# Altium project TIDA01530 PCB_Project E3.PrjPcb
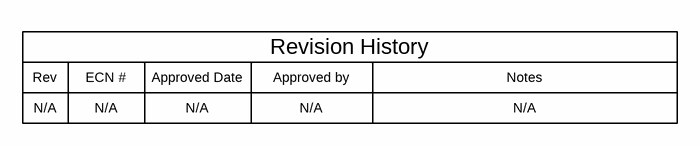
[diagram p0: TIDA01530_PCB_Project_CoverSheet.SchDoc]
CopyrightYear: 2018; PCB_Layout: C.Kinnaird; PCB_Rev: E3; PRJ_Customer: Public Release; PRJ_Engineer: C.Kinnaird; PRJ_Number: TIDA-01530; PRJ_Title: Automotive Windshield Wiper Drive; SCH_Rev: E3; TechSupport: http://www.ti.com/support; TID: 01530
4 sheets, 149 parts. Net scope: global (net labels, ports and power ports of the same name join across sheets).
Board file: TIDA01530E3.PcbDoc
Sheets:
  TIDA01530_PCB_Project_CoverSheet.SchDoc
  TIDA01530 Front Wipers 2x 8702D v2.SchDoc
  TIDA01530 Rear Wipers.SchDoc
  TIDA01530 Switches Connectors.SchDoc

## Sheet TIDA01530_PCB_Project_CoverSheet.SchDoc
size 431 x 279 mm; Date: Not shown in title block; ApprovedBy: Not shown in title block; CheckedBy: Not shown in title block; Author: Not shown in title block; CompanyName: Not shown in title block; Engineer: Not shown in title block; Organization: Not shown in title block; Address1: Not shown in title block; Address2: Not shown in title block; Address3: Not shown in title block; Address4: Not shown in title block; DocumentNumber: 1; Revision: Use project parameter SCH_Rev; SheetNumber: 1; SheetTotal: 4; PageSetup: Record=PageOptions¦CenterHorizontal=True¦CenterVertical=True¦PrintScale=1.00¦XCorrection=1.00¦YCorrection=1.00¦PrintKind=0¦BorderSize=5000000¦LeftOffset=0¦BottomOffset=0¦Orientation=2¦PaperLength=1000¦PaperWidth=1000¦Scale=100¦PaperSource=15¦PrintQuality=600¦MediaType=1¦DitherType=10¦PaperKind=Letter¦PrintScaleMode=1

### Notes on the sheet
- Rev
- N/A
- ECN #
- Approved Date
- Approved by
- Revision History
- Notes

## Sheet TIDA01530 Front Wipers 2x 8702D v2.SchDoc
size 431 x 279 mm; Date: Not shown in title block; ApprovedBy: Not shown in title block; CheckedBy: Not shown in title block; Author: Not shown in title block; CompanyName: Not shown in title block; Engineer: Not shown in title block; Organization: Not shown in title block; Address1: Not shown in title block; Address2: Not shown in title block; Address3: Not shown in title block; Address4: Not shown in title block; DocumentNumber: 1; Revision: Use project parameter SCH_Rev; SheetNumber: 2; SheetTotal: 4; PageSetup: Record=PageOptions¦CenterHorizontal=True¦CenterVertical=True¦PrintScale=1.00¦XCorrection=1.00¦YCorrection=1.00¦PrintKind=0¦BorderSize=5000000¦LeftOffset=0¦BottomOffset=0¦Orientation=2¦PaperLength=1000¦PaperWidth=1000¦Scale=100¦PaperSource=15¦PrintQuality=600¦MediaType=1¦DitherType=10¦PaperKind=Letter¦PrintScaleMode=1
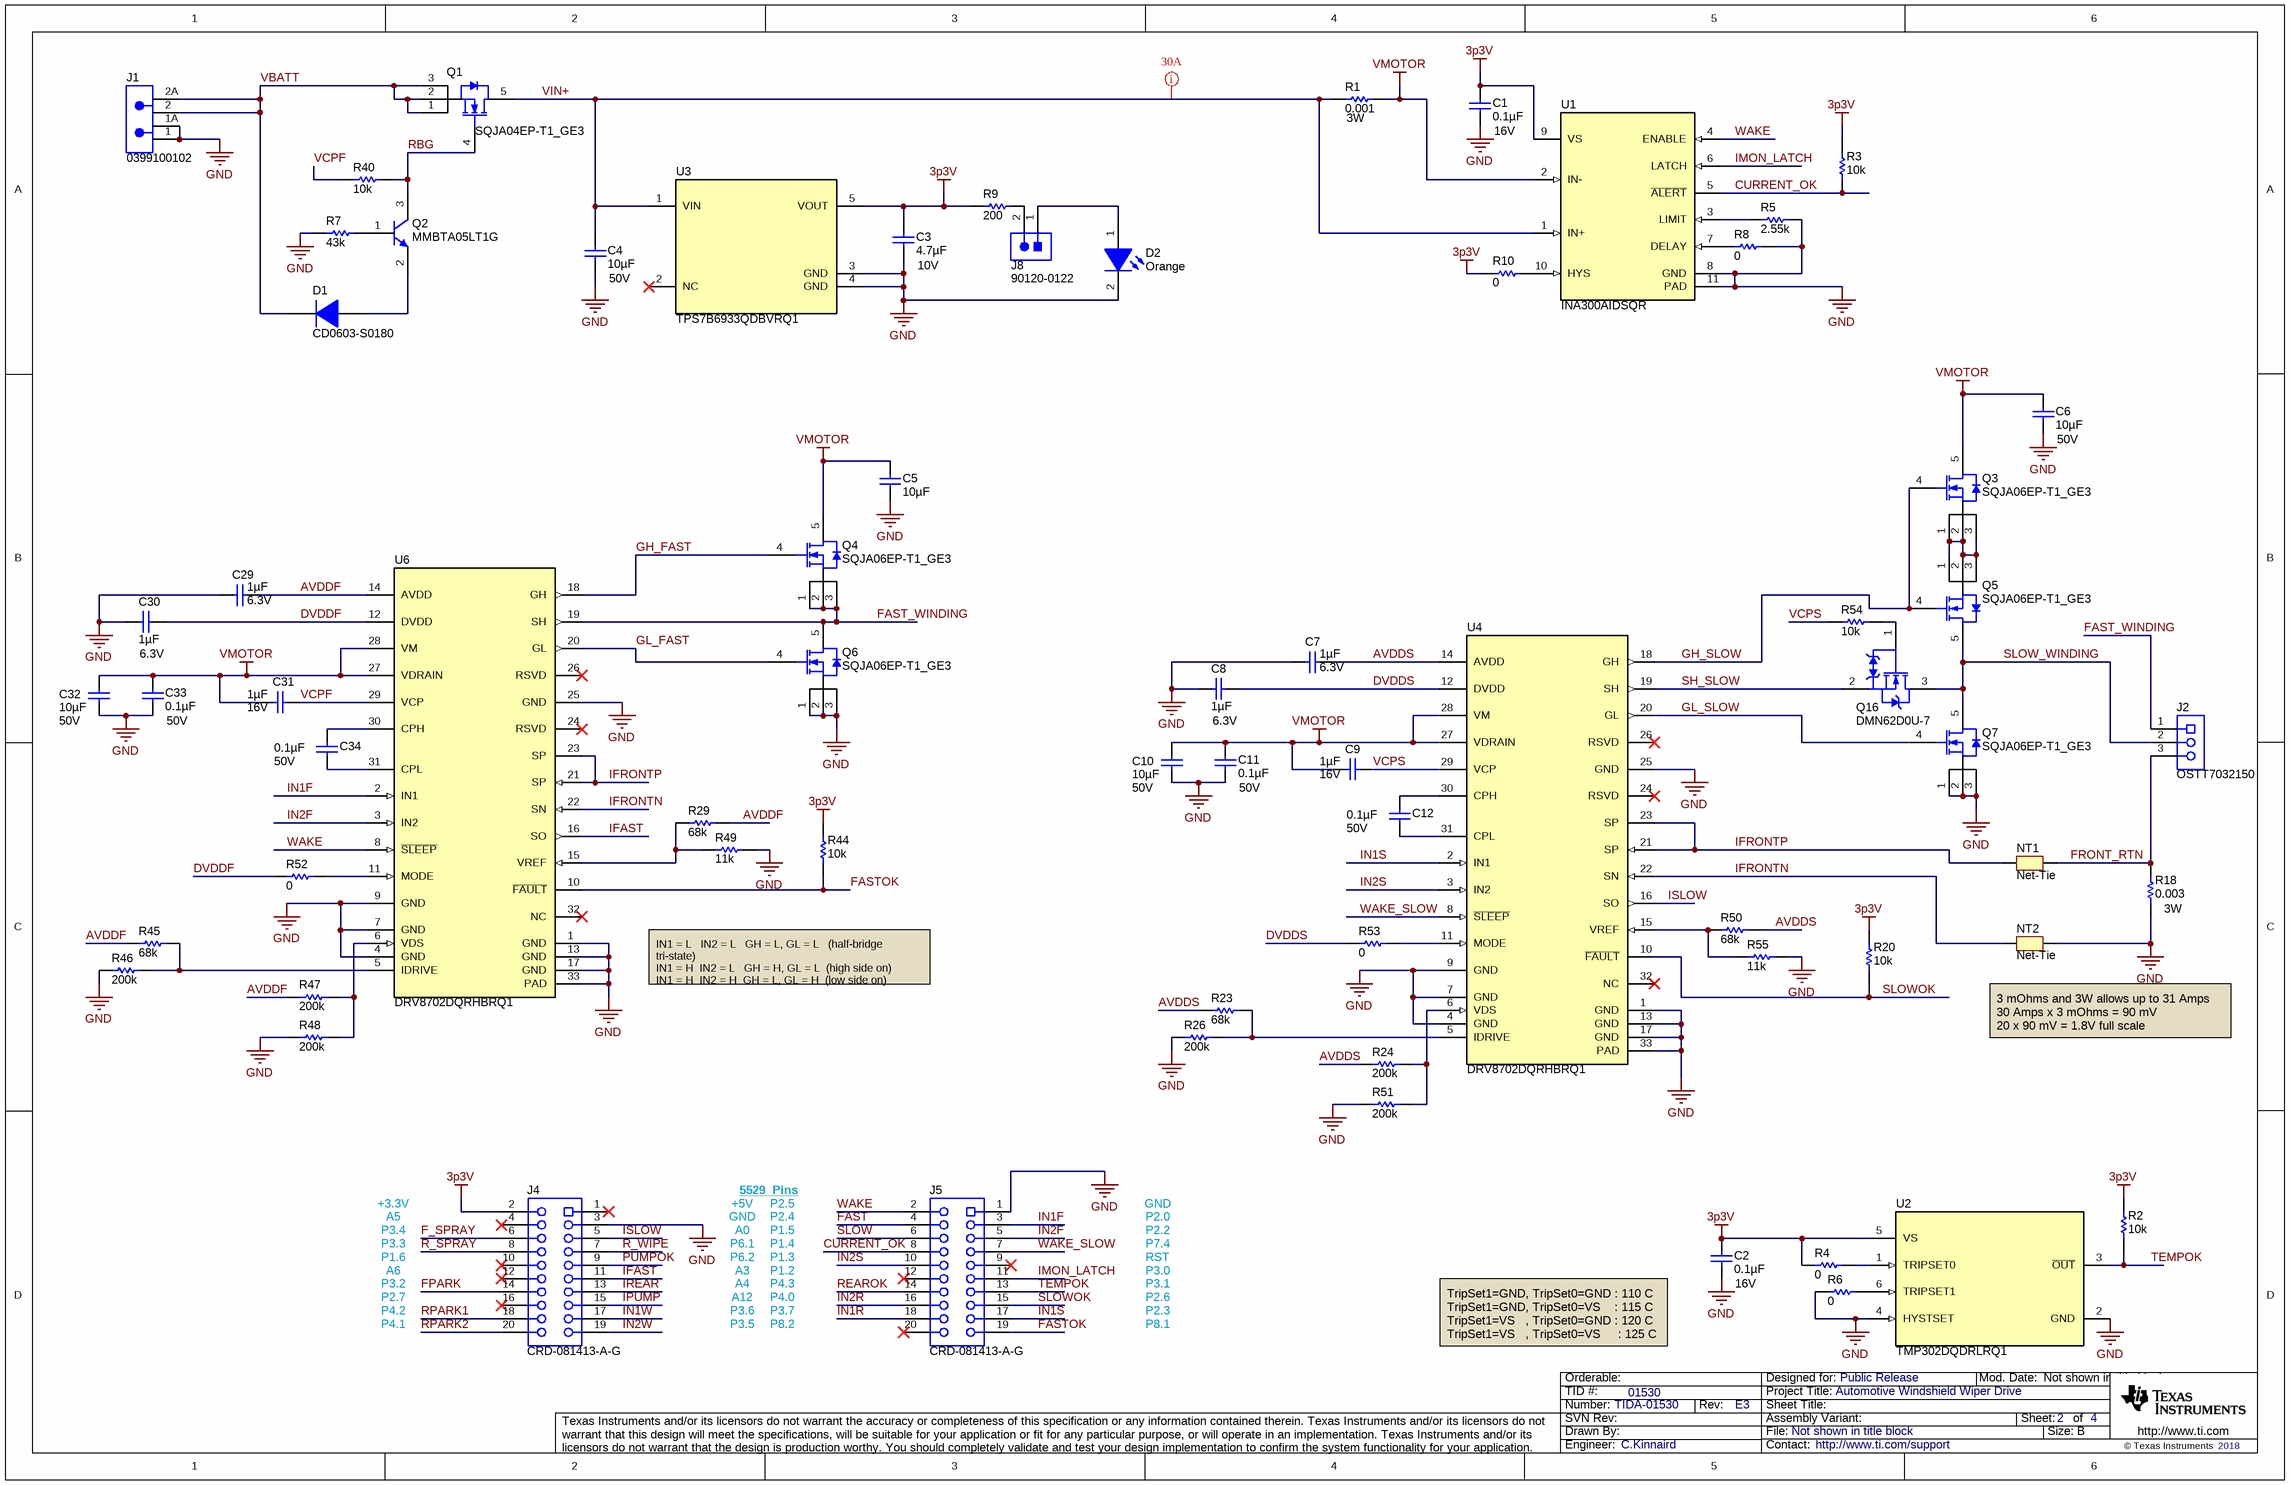
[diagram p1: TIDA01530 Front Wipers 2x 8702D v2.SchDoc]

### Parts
C1  ValueDisplayed: 0.1µF  Value2: 16V  [0402]  (hidden comment: C0402C104K4RACAUTO)
C2  ValueDisplayed: 0.1µF  Value2: 16V  [0402]  (hidden comment: C0402C104K4RACAUTO)
C3  ValueDisplayed: 4.7µF  Value2: 10V  [0805_HV]  (hidden comment: C2012X7R1A475M125AC)
C4  ValueDisplayed: 10µF  Value2: 50V  [1210_280]  (hidden comment: UMK325AB7106KMHT)
C5  ValueDisplayed: 10µF  [1206_180]  (hidden comment: CL31B106KBHNNNE)
C6  ValueDisplayed: 10µF  Value2: 50V  [1206_180]  (hidden comment: CL31B106KBHNNNE)
C7  ValueDisplayed: 1µF  Value2: 6.3V  [0603]  (hidden comment: GRM188R70J105KA01D)
C8  ValueDisplayed: 1µF  Value2: 6.3V  [0603]  (hidden comment: GRM188R70J105KA01D)
C9  ValueDisplayed: 1µF  Value2: 16V  [0603]  (hidden comment: C1608X7R1C105K080AC)
C10  ValueDisplayed: 10µF  Value2: 50V  [1210_280]  (hidden comment: C3225X7S1H106K250AB)
C11  ValueDisplayed: 0.1µF  Value2: 50V  [0603]  (hidden comment: C1608X7R1H104K080AA)
C12  ValueDisplayed: 0.1µF  Value2: 50V  [0603]  (hidden comment: C1608X7R1H104K080AA)
C29  ValueDisplayed: 1µF  Value2: 6.3V  [0603]  (hidden comment: GRM188R70J105KA01D)
C30  ValueDisplayed: 1µF  Value2: 6.3V  [0603]  (hidden comment: GRM188R70J105KA01D)
C31  ValueDisplayed: 1µF  Value2: 16V  [0603]  (hidden comment: C1608X7R1C105K080AC)
C32  ValueDisplayed: 10µF  Value2: 50V  [1210_280]  (hidden comment: C3225X7S1H106K250AB)
C33  ValueDisplayed: 0.1µF  Value2: 50V  [0603]  (hidden comment: C1608X7R1H104K080AA)
C34  ValueDisplayed: 0.1µF  Value2: 50V  [0603]  (hidden comment: C1608X7R1H104K080AA)
D1  CD0603-S0180  [Diode_0603]
D2  value Orange  [LTST-C191_Orange]  (hidden comment: LTST-C191KFKT)
J1  0399100102  [CONN_399100102]
J2  OSTT7032150  [On-Shore_OSTT7032150]
J4  CRD-081413-A-G  [Major_CRD-081413-A-x]
J5  CRD-081413-A-G  [Major_CRD-081413-A-x]
J8  90120-0122  [CONN_90120-0122]
NT1  Net-Tie  [Net-Tie_10mil]  (net tie, no BOM)
NT2  Net-Tie  [Net-Tie_10mil]  (net tie, no BOM)
Q1  SQJA04EP-T1_GE3  [PowerPAK_SO-8L]
Q2  MMBTA05LT1G  [SOT-23]
Q3  SQJA06EP-T1_GE3  [PowerPAK_SO-8L]
Q4  SQJA06EP-T1_GE3  [PowerPAK_SO-8L]
Q5  SQJA06EP-T1_GE3  [PowerPAK_SO-8L]
Q6  SQJA06EP-T1_GE3  [PowerPAK_SO-8L]
Q7  SQJA06EP-T1_GE3  [PowerPAK_SO-8L]
Q16  DMN62D0U-7  [SOT-23]
R1  ValueDisplayed: 0.001  Value2: 3W  [CRE2512-R1_R4]  (hidden comment: CRE2512-FZ-R001E-3)
R2  ValueDisplayed: 10k  [0402]  (hidden comment: CRCW040210K0JNED)
R3  ValueDisplayed: 10k  [0402]  (hidden comment: CRCW040210K0JNED)
R4  ValueDisplayed: 0  [0402]  (hidden comment: ERJ-2GE0R00X)
R5  ValueDisplayed: 2.55k  [0402]  (hidden comment: CRCW04022K55FKED)
R6  ValueDisplayed: 0  [0402]  (hidden comment: ERJ-2GE0R00X)
R7  ValueDisplayed: 43k  [0402]  (hidden comment: CRCW040243K0JNED)
R8  ValueDisplayed: 0  [0402]  (hidden comment: ERJ-2GE0R00X)
R9  ValueDisplayed: 200  [0603]  (hidden comment: CRCW0603200RJNEA)
R10  ValueDisplayed: 0  [0402]  (hidden comment: ERJ-2GE0R00X)
R18  ValueDisplayed: 0.003  Value2: 3W  [CRE2512-R1_R4]  (hidden comment: CRE2512-FZ-R003E-3)
R20  ValueDisplayed: 10k  [0402]  (hidden comment: CRCW040210K0JNED)
R23  ValueDisplayed: 68k  [0402]  (hidden comment: CRCW040268K0JNED)
R24  ValueDisplayed: 200k  [0402]  (hidden comment: CRCW0402200KJNED)
R26  ValueDisplayed: 200k  [0402]  (hidden comment: CRCW0402200KJNED)
R29  ValueDisplayed: 68k  [0402]  (hidden comment: CRCW040268K0JNED)
R40  ValueDisplayed: 10k  [0402]  (hidden comment: CRCW040210K0JNED)
R44  ValueDisplayed: 10k  [0402]  (hidden comment: CRCW040210K0JNED)
R45  ValueDisplayed: 68k  [0402]  (hidden comment: CRCW040268K0JNED)
R46  ValueDisplayed: 200k  [0402]  (hidden comment: CRCW0402200KJNED)
R47  ValueDisplayed: 200k  [0402]  (hidden comment: CRCW0402200KJNED)
R48  ValueDisplayed: 200k  [0402]  (hidden comment: CRCW0402200KJNED)
R49  ValueDisplayed: 11k  [0402]  (hidden comment: CRCW040211K0JNED)
R50  ValueDisplayed: 68k  [0402]  (hidden comment: CRCW040268K0JNED)
R51  ValueDisplayed: 200k  [0402]  (hidden comment: CRCW0402200KJNED)
R52  ValueDisplayed: 0  [0402]  (hidden comment: ERJ-2GE0R00X)
R53  ValueDisplayed: 0  [0402]  (hidden comment: ERJ-2GE0R00X)
R54  ValueDisplayed: 10k  [0402]  (hidden comment: CRCW040210K0JNED)
R55  ValueDisplayed: 11k  [0402]  (hidden comment: CRCW040211K0JNED)
U1  INA300AIDSQR  [DSQ0010A]
U2  TMP302DQDRLRQ1  [DRL0006A]
U3  TPS7B6933QDBVRQ1  [DBV0005A_N]
U4  DRV8702DQRHBRQ1  [RHB0032E]
U6  DRV8702DQRHBRQ1  [RHB0032E]

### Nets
3p3V: C1.1 C2.1 C3.1 J4.2 R2.2 R3.2 R4.1 R9.1 R10.1 R20.1 R44.1 U1.9(VS) U2.5(VS) U3.5(VOUT)
GND: C1.2 C2.2 C3.2 C4.2 C5.2 C6.2 C7.2 C8.2 C10.2 C11.2 C29.2 C30.2 C32.2 C33.2 D2.2(K) J1.1 J1.1A J4.3 J5.1 NT2.2 Q6.1(S) Q6.2(S) Q6.3(S) Q7.1(S) Q7.2(S) Q7.3(S) R5.2 R6.1 R7.1 R8.2 R18.1 R26.2 R46.2 R48.1 R49.2 R51.1 R55.2 U1.8(GND) U1.11(PAD) U2.2(GND) U2.4(HYSTSET) U3.3(GND) U3.4(GND) U4.1(GND) U4.4(GND) U4.7(GND) U4.9(GND) U4.13(GND) U4.17(GND) U4.25(GND) U4.33(PAD) U6.1(GND) U6.4(GND) U6.7(GND) U6.9(GND) U6.13(GND) U6.17(GND) U6.25(GND) U6.33(PAD)
VMOTOR: C5.1 C6.1 C9.1 C10.1 C11.1 C31.1 C32.1 C33.1 Q3.5(D) Q4.5(D) R1.2 U1.2(IN-) U4.27(VDRAIN) U4.28(VM) U6.27(VDRAIN) U6.28(VM)
AVDDF: C29.1 R29.1 R45.2 R47.1 U6.14(AVDD)
AVDDS: C7.1 R23.2 R24.1 R50.1 U4.14(AVDD)
CURRENT_OK: J5.8 R3.1 U1.5(~{ALERT})
DVDDF: C30.1 R52.1 U6.12(DVDD)
DVDDS: C8.1 R53.1 U4.12(DVDD)
F_SPRAY: J4.6
FAST: J5.4
FAST_WINDING: J2.1 Q4.1(S) Q4.2(S) Q4.3(S) Q6.5(D) U6.19(SH)
FASTOK: J5.19 R44.2 U6.10(~{FAULT})
FPARK: J4.14
FRONT_RTN: J2.3 NT1.2 R18.2
GH_FAST: Q4.4(G) U6.18(GH)
GH_SLOW: Q3.4(G) Q5.4(G) U4.18(GH)
GL_FAST: Q6.4(G) U6.20(GL)
GL_SLOW: Q7.4(G) U4.20(GL)
IFAST: J4.11 U6.16(SO)
IFRONTN: NT2.1 U4.22(SN) U6.22(SN)
IFRONTP: NT1.1 U4.21(SP) U4.23(SP) U6.21(SP) U6.23(SP)
IMON_LATCH: J5.11 U1.6(LATCH)
IN1F: J5.3 U6.2(IN1)
IN1R: J5.18
IN1S: J5.17 U4.2(IN1)
IN1W: J4.17
IN2F: J5.5 U6.3(IN2)
IN2R: J5.16
IN2S: J5.10 U4.3(IN2)
IN2W: J4.19
IPUMP: J4.15
IREAR: J4.13
ISLOW: J4.5 U4.16(SO)
PUMPOK: J4.9
R_SPRAY: J4.8
R_WIPE: J4.7
RBG: Q1.4(G) Q2.3(C) R40.1
REAROK: J5.14
RPARK1: J4.18
RPARK2: J4.20
SH_SLOW: Q16.2(S) U4.19(SH)
SLOW: J5.6
SLOW_WINDING: J2.2 Q5.5(D) Q7.5(D) Q16.3(D)
SLOWOK: J5.15 R20.2 U4.10(~{FAULT})
TEMPOK: J5.13 R2.1 U2.3(~{OUT})
VBATT: D1.1(K) J1.2 J1.2A Q1.1(S) Q1.2(S) Q1.3(S)
VCPF: C31.2 R40.2 U6.29(VCP)
VCPS: C9.2 R54.2 U4.29(VCP)
VIN+: C4.1 Q1.5(D) R1.1 U1.1(IN+) U3.1(VIN)
WAKE: J5.2 U1.4(ENABLE) U6.8(~{SLEEP})
WAKE_SLOW: J5.7 U4.8(~{SLEEP})
NetC12_1: C12.1 U4.30(CPH)
NetC12_2: C12.2 U4.31(CPL)
NetC34_1: C34.1 U6.30(CPH)
NetC34_2: C34.2 U6.31(CPL)
NetD1_2: D1.2(A) Q2.2(E)
NetD2_1: D2.1(A) J8.1
NetJ8_2: J8.2 R9.2
NetQ2_1: Q2.1(B) R7.2
NetQ3_1: Q3.1(S) Q3.2(S) Q3.3(S) Q5.1(S) Q5.2(S) Q5.3(S)
NetQ16_1: Q16.1(G) R54.1
NetR4_2: R4.2 U2.1(TRIPSET0)
NetR5_1: R5.1 U1.3(LIMIT)
NetR6_2: R6.2 U2.6(TRIPSET1)
NetR8_1: R8.1 U1.7(DELAY)
NetR10_2: R10.2 U1.10(HYS)
NetR23_1: R23.1 R26.1 U4.5(IDRIVE)
NetR24_2: R24.2 R51.2 U4.6(VDS)
NetR29_2: R29.2 R49.1 U6.15(VREF)
NetR45_1: R45.1 R46.1 U6.5(IDRIVE)
NetR47_2: R47.2 R48.2 U6.6(VDS)
NetR50_2: R50.2 R55.1 U4.15(VREF)
NetR52_2: R52.2 U6.11(MODE)
NetR53_2: R53.2 U4.11(MODE)

Not connected (* = marked no-connect by the designer): J4 1* 4* 10* 12* 16*; J5 9* 12* 20*; U3 2(NC)*; U4 24(RSVD)* 26(RSVD)* 32(NC)*; U6 24(RSVD)* 26(RSVD)* 32(NC)*

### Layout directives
rule Undefined: VIN+

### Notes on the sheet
- IN1 = L   IN2 = L   GH = L, GL = L   (half-bridge tri-state)
  IN1 = H  IN2 = L   GH = H, GL = L  (high side on)
  IN1 = H  IN2 = H  GH = L, GL = H  (low side on)
- (near NT2) 3 mOhms and 3W allows up to 31 Amps
  30 Amps x 3 mOhms = 90 mV
  20 x 90 mV = 1.8V full scale
- +3.3V
- A5
- P3.4
- +5V
- GND
- A0
- 5529  Pins
- P2.5
- P2.4
- P1.5
- P2.0
- P2.2
- P3.3
- P1.6
- A6
- P3.2
- P2.7
- P6.1
- P6.2
- A3
- A4
- A12
- P1.4
- P1.3
- P1.2
- P4.3
- P4.0
- P7.4
- RST
- P3.0
- P3.1
- P2.6
- P4.2
- P4.1
- P3.6
- P3.5
- P3.7
- P8.2
- P2.3
- P8.1
- TripSet1=GND, TripSet0=GND : 110 C
  TripSet1=GND, TripSet0=VS    : 115 C
  TripSet1=VS   , TripSet0=GND : 120 C
  TripSet1=VS   , TripSet0=VS     : 125 C

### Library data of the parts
C1 C2 = C0402C104K4RACAUTO: CAP, CERM, 0.1 µF, 16 V,+/- 10%, X7R, AEC-Q200 Grade 1, 0402; Manufacturer: Kemet; Polarized: N; CompType: Capacitor; Value: 0.1uF; U/M: EA; Cap_F: 0.0000001; Tolerance_%: 10; VDC_V: 16; TaMin_C: -55; TaMax_C: 125; SizeArea_mm2: 0.5; SizeAreaWB_mm2: 3; SizeX_mm: 1; SizeZ_mm: 0.6; AEC Category: Q200; AEC Qualified: Y; Green_Lifecycle: Active; Green_REACh: Passed
C3 = C2012X7R1A475M125AC: CAP, CERM, 4.7 µF, 10 V,+/- 20%, X7R, 0805; Manufacturer: TDK; Polarized: N; CompType: Capacitor; Value: 4.7uF; U/M: EA; Cap_F: 0.0000047; Tolerance_%: 20; VDC_V: 10; TaMin_C: -55; TaMax_C: 125; Cap_Case: 0805; SizeArea_mm2: 2.5; SizeAreaWB_mm2: 6.75; SizeX_mm: 2; SizeY_mm: 1.25; SizeZ_mm: 1.45; AEC Category: Q200; Green_Lifecycle: Active; Green_REACh: Passed
C4 = UMK325AB7106KMHT: CAP, CERM, 10 µF, 50 V,+/- 10%, X7R, AEC-Q200 Grade 1, 1210; Manufacturer: Taiyo Yuden; Polarized: N; CompType: Capacitor; Value: 10uF; U/M: EA; Cap_F: 0.00001; Tolerance_%: 10; VDC_V: 50; TaMin_C: -55; TaMax_C: 125; Cap_Case: 1210; SizeArea_mm2: 8; SizeAreaWB_mm2: 14.7; SizeX_mm: 3.2; SizeY_mm: 2.5; SizeZ_mm: 2.8; AEC Category: Q200; AEC Qualified: Y; AEC Grade: 1
C5 = CL31B106KBHNNNE: CAP, CERM, 10 µF, 50 V,+/- 10%, X7R, 1206; Manufacturer: Samsung Electro-Mechanics; Polarized: N; CompType: Capacitor; Value: 10uF; U/M: EA; Cap_F: 0.00001; Tolerance_%: 10; VDC_V: 50; Value2: 50V; TaMin_C: -55; TaMax_C: 125; Cap_Case: 1206; SizeArea_mm2: 5.12; SizeAreaWB_mm2: 10.92; SizeX_mm: 3.2; SizeY_mm: 1.6; SizeZ_mm: 1.8; AEC Category: Q200
C6 = CL31B106KBHNNNE: CAP, CERM, 10 µF, 50 V,+/- 10%, X7R, 1206; Manufacturer: Samsung Electro-Mechanics; Polarized: N; CompType: Capacitor; Value: 10uF; U/M: EA; Cap_F: 0.00001; Tolerance_%: 10; VDC_V: 50; TaMin_C: -55; TaMax_C: 125; Cap_Case: 1206; SizeArea_mm2: 5.12; SizeAreaWB_mm2: 10.92; SizeX_mm: 3.2; SizeY_mm: 1.6; SizeZ_mm: 1.8; AEC Category: Q200
C7 C8 C29 C30 = GRM188R70J105KA01D: CAP, CERM, 1 µF, 6.3 V,+/- 10%, X7R, 0603; Manufacturer: MuRata; Polarized: N; CompType: Capacitor; Value: 1uF; U/M: EA; Cap_F: 0.000001; Tolerance_%: 10; VDC_V: 6.3; TaMin_C: -55; TaMax_C: 125; SizeArea_mm2: 1.28; SizeAreaWB_mm2: 4.68; SizeX_mm: 1.6; SizeY_mm: 0.8; SizeZ_mm: 1; AEC Category: Q200; Green_Lifecycle: Active; Green_REACh: Passed
C9 C31 = C1608X7R1C105K080AC: CAP, CERM, 1 µF, 16 V,+/- 10%, X7R, 0603; Manufacturer: TDK; Polarized: N; CompType: Capacitor; Value: 1uF; U/M: EA; Cap_F: 0.000001; Tolerance_%: 10; ESR_ohm: 0.0057; Value1: 0.0057 ohm; VDC_V: 16; TaMin_C: -55; TaMax_C: 125; SizeArea_mm2: 1.28; SizeAreaWB_mm2: 4.68; SizeX_mm: 1.6; SizeY_mm: 0.8; SizeZ_mm: 1; AEC Category: Q200; Green_Lifecycle: Active; Green_REACh: Passed
C10 C32 = C3225X7S1H106K250AB: CAP, CERM, 10 µF, 50 V,+/- 10%, X7S, 1210; Manufacturer: TDK; Polarized: N; CompType: Capacitor; Value: 10uF; U/M: EA; Cap_F: 0.00001; Tolerance_%: 10; ESR_ohm: 0.002827; Value1: 0.002827 ohm; VDC_V: 50; IRMS_A: 4.37286; TaMin_C: -55; TaMax_C: 125; Cap_Case: 1210; SizeArea_mm2: 8; SizeAreaWB_mm2: 14.7; SizeX_mm: 3.2; SizeY_mm: 2.5; SizeZ_mm: 2.8; AEC Category: Q200; Green_Lifecycle: Active; Green_REACh: Passed
C11 C12 C33 C34 = C1608X7R1H104K080AA: CAP, CERM, 0.1 µF, 50 V,+/- 10%, X7R, 0603; Manufacturer: TDK; Polarized: N; CompType: Capacitor; Value: 0.1uF; U/M: EA; Cap_F: 0.0000001; Tolerance_%: 10; ESR_ohm: 0.0296; Value1: 0.0296 ohm; VDC_V: 50; IRMS_A: 0.97199; TaMin_C: -55; TaMax_C: 125; SizeArea_mm2: 1.28; SizeAreaWB_mm2: 4.68; SizeX_mm: 1.6; SizeY_mm: 0.8; SizeZ_mm: 1; AEC Category: Q200; Green_Lifecycle: NRND; Green_REACh: Passed
D1 = CMP-0029009-1: Diode, Switching, 90 V, 0.1 A, 0603 Diode; Manufacturer: Bourns; Io_A: 1dA; Green_Lifecycle: Not Set; SizeAreaWB_mm2: 5.13; Vr_V: 90V; Green_REACh: Incomplete; Value1: 0.1A; TJmax_C: 125°C; U/M: EA; Value: 90V; SizeZ_mm: 0.75; SizeX_mm: 1.7; SizeY_mm: 0.9; Vf_V: 1V; SizeArea_mm2: 1.53; AEC Category: Q101
D2 = LTST-C191KFKT: LED, Orange, SMD; Manufacturer: Lite-On; Type: AlInGaP; Vf_V: 2; Value2: 2V; Io_A: 0.02; Vr_V: 5; Ir_A: 1e-005; Tjmax_C: 85; Power_TotalModule: 0.075; Value1: 0.075W; Angle: 130; U/M: EA; Green_Lifecycle: Not Set; Green_REACh: Incomplete
J1 = 0399100102: Terminal Block, 60A, 10.16mm Pitch, 2-Pos, TH; Manufacturer: Molex; SymbolCreator: a0799628
J2 = OSTT7032150: Terminal Block, 3x1, 9.52mm, TH; Manufacturer: On-Shore Technology; SymbolCreator: a0412235; Pitch_mm: 9.52; Gender: Female; Row_Count: 1; ContactFinish: Brass; Green_Lifecycle: Not Set; Green_REACh: Incomplete
J4 J5 = CRD-081413-A-G: Receptacle, 2.54 mm, 10x2, Gold, TH; Manufacturer: Major League Electronics; SymbolCreator: a0412235; Green_Lifecycle: Not Set; Green_REACh: Incomplete
J8 = 90120-0122: Header, 100mil, 2x1, Tin, TH; Manufacturer: Molex; SymbolCreator: a0412235; Green_Lifecycle: Active; Green_REACh: Passed
NT1 NT2 = Net-Tie: Single point connection between nets.; SymbolCreator: codlsc
Q1 = CMP-0077286-1: MOSFET, N-CH, 60 V, 75 A, AEC-Q101, PowerPAK_SO-8L; Manufacturer: Vishay-Siliconix; Alternate Manufacturer: None; ChType: N; QgTyp_nC: 35.0; SizeAreaWB_mm2: 58.1095; SizeArea_mm2: 31.5495; IdsMax_A: 75A; AEC Qualified: Y; VdsMax_V: 60V; Vgs_V: 20V; AEC Category: Q101; Value: 60V; SizeZ_mm: 1.14; SizeY_mm: 5.13; Value2: 35 nC; U/M: EA; Value1: ? ohm; SizeX_mm: 6.15
Q2 = MMBTA05LT1G, ON Semiconductor: Transistor, NPN, 60 V, 0.5 A, AEC-Q101, SOT-23; CompType: BJT; PNP: 0; NPN: 1; Vceo_V: 60; Vcesat1_V: 0.25; Value: 60 V; IcRated_A: 0.5; Value1: 0.5 A; TaMin_C: -55; TaMax_C: 150; SizeAreaWB_mm2: 14; SizeArea_mm2: 7.5; SizeX_mm: 2.5; SizeY_mm: 3; SizeZ_mm: 1.1; U/M: EA; AEC Category: Q101; AEC Qualified: Y
Q3-Q7 = CMP-0077287-1: MOSFET, N-CH, 60 V, 57 A, AEC-Q101, PowerPAK_SO-8L; Manufacturer: Vishay-Siliconix; Alternate Manufacturer: None; ChType: N; QgTyp_nC: 27.0; SizeAreaWB_mm2: 58.1095; SizeArea_mm2: 31.5495; IdsMax_A: 57A; AEC Qualified: Y; VdsMax_V: 60V; Vgs_V: 20V; AEC Category: Q101; Value: 60V; SizeZ_mm: 1.14; SizeY_mm: 5.13; Value2: 27 nC; U/M: EA; Value1: ? ohm; SizeX_mm: 6.15
Q16 = DMN62D0U-7: MOSFET, N-CH, 60 V, 0.38 A, AEC-Q101, SOT-23; Manufacturer: Diodes Inc.; Alternate Manufacturer: None; SymbolCreator: x0208325; U/M: EA; ChType: N; Value: 60V; VdsMax_V: 60; Value1: 2 ohm; Rdson45_ohm: 2; Value2: 0.5 nC; QgTyp_nC: 0.5; Vgs_V: 20; IdsMax_A: 0.38; SizeAreaWB_mm2: 14; SizeArea_mm2: 7.5; SizeX_mm: 2.5; SizeY_mm: 3; SizeZ_mm: 1.1; AEC Category: Q101; AEC Qualified: Y
R1 = CRE2512-FZ-R001E-3: RES, 0.001, 1%, 3 W, AEC-Q200 Grade 0, 2512; Manufacturer: Bourns; CompType: Resistor; Value: 0.001; Value_Code: 1L000; Tolerance_%: 1; Power_W: 3; TempCo: 50 ppm/C; SizeArea_mm2: 21.6075; SizeX_mm: 6.45; SizeY_mm: 3.35; SizeZ_mm: 0.9; EIA_Code: E96; U/M: EA; AEC Category: Q200; AEC Qualified: Y; AEC Grade: 0
R2 R3 R20 R40 R44 R54 = CRCW040210K0JNED: RES, 10 k, 5%, 0.063 W, 0402; Manufacturer: Vishay-Dale; CompType: Resistor; Value: 10k; Res_ohm: 10000; Value_Code: 10k0; Tolerance_%: 5; Power_W: 0.063; Value2: 0.063W; VDC_V: 50; TempCo: 200 ppm/C; SizeArea_mm2: 0.5; SizeX_mm: 1; SizeZ_mm: 0.6; EIA_Code: E24; U/M: EA; AEC Category: Q200; Green_Lifecycle: Active; Green_REACh: Passed
R4 R6 R8 R10 R52 R53 = ERJ-2GE0R00X: RES, 0, 5%, 0.063 W, 0402; Manufacturer: Panasonic; CompType: Resistor; Value: 0; Value_Code: 0000; Tolerance_%: 5; Power_W: 0.063; Value2: 0.063W; VDC_V: 50; TempCo: 600 ppm/C; SizeArea_mm2: 0.5; SizeX_mm: 1; SizeZ_mm: 0.6; EIA_Code: E24; U/M: EA; AEC Category: Q200; Green_Lifecycle: Active; Green_REACh: Passed
R5 = CRCW04022K55FKED: RES, 2.55 k, 1%, 0.063 W, 0402; Manufacturer: Vishay-Dale; CompType: Resistor; Value: 2.55k; Res_ohm: 2550; Value_Code: 2k55; Tolerance_%: 1; Power_W: 0.063; Value2: 0.063W; VDC_V: 50; TempCo: 100 ppm/C; SizeArea_mm2: 0.5; SizeZ_mm: 0.6; EIA_Code: E96; U/M: EA; AEC Category: Q200
R7 = CRCW040243K0JNED: RES, 43 k, 5%, 0.063 W, 0402; Manufacturer: Vishay-Dale; CompType: Resistor; Value: 43k; Res_ohm: 43000; Value_Code: 43k0; Tolerance_%: 5; Power_W: 0.063; Value2: 0.063W; VDC_V: 50; TempCo: 200 ppm/C; SizeArea_mm2: 0.5; SizeX_mm: 1; SizeZ_mm: 0.6; EIA_Code: E24; U/M: EA; AEC Category: Q200
R9 = CRCW0603200RJNEA: RES, 200, 5%, 0.1 W, 0603; Manufacturer: Vishay-Dale; CompType: Resistor; Value: 200; Value_Code: 200R; Tolerance_%: 5; Power_W: 0.1; Value2: 0.1W; VDC_V: 75; TempCo: 200 ppm/C; SizeArea_mm2: 1.28; SizeX_mm: 1.6; SizeY_mm: 0.8; SizeZ_mm: 1; EIA_Code: E24; U/M: EA; AEC Category: Q200; Green_Lifecycle: Active; Green_REACh: Passed
R18 = CRE2512-FZ-R003E-3: RES, 0.003, 1%, 3 W, AEC-Q200 Grade 0, 2512; Manufacturer: Bourns; CompType: Resistor; Value: 0.003; Value_Code: 3L000; Tolerance_%: 1; Power_W: 3; TempCo: 50 ppm/C; SizeArea_mm2: 21.6075; SizeX_mm: 6.45; SizeY_mm: 3.35; SizeZ_mm: 0.9; EIA_Code: E96; U/M: EA; AEC Category: Q200; AEC Qualified: Y; AEC Grade: 0
R23 R29 R45 R50 = CRCW040268K0JNED: RES, 68 k, 5%, 0.063 W, 0402; Manufacturer: Vishay-Dale; CompType: Resistor; Value: 68k; Res_ohm: 68000; Value_Code: 68k0; Tolerance_%: 5; Power_W: 0.063; Value2: 0.063W; VDC_V: 50; TempCo: 200 ppm/C; SizeArea_mm2: 0.5; SizeX_mm: 1; SizeZ_mm: 0.6; EIA_Code: E24; U/M: EA; AEC Category: Q200
R24 R26 R46-R48 R51 = CRCW0402200KJNED: RES, 200 k, 5%, 0.063 W, 0402; Manufacturer: Vishay-Dale; CompType: Resistor; Value: 200k; Res_ohm: 200000; Tolerance_%: 5; Power_W: 0.063; Value2: 0.063W; VDC_V: 50; TempCo: 200 ppm/C; SizeArea_mm2: 0.5; SizeX_mm: 1; SizeZ_mm: 0.6; EIA_Code: E24; U/M: EA; AEC Category: Q200; Green_Lifecycle: Active; Green_REACh: Passed
R49 R55 = CRCW040211K0JNED: RES, 11 k, 5%, 0.063 W, 0402; Manufacturer: Vishay-Dale; CompType: Resistor; Value: 11k; Res_ohm: 11000; Value_Code: 11k0; Tolerance_%: 5; Power_W: 0.063; Value2: 0.063W; VDC_V: 50; TempCo: 200 ppm/C; SizeArea_mm2: 0.5; SizeX_mm: 1; SizeZ_mm: 0.6; EIA_Code: E24; U/M: EA; AEC Category: Q200
U1 = INA300AIDSQR: 36-V Low-/High-Side, Overcurrent Protection Comparator, DSQ0010A (WSON-10); Alternate PartNumber: INA300AIDSQT; Manufacturer: Texas Instruments; SymbolCreator: a0411947; SizeArea_mm2: 4; SizeAreaWB_mm2: 9; SizeX_mm: 2; SizeZ_mm: 0.8; CompType: IC; U/M: EA
U2 = TMP302DQDRLRQ1: Automotive, Pin-Selectable Trip Point 1.4V-Capable Family of Temperature Switches, DRL0006A (SOT-OTHER-6); Manufacturer: Texas Instruments; SymbolCreator: Altium; SizeArea_mm2: 2.56; SizeAreaWB_mm2: 6.76; SizeX_mm: 1.6; SizeZ_mm: 0.6; CompType: IC; U/M: EA
U3 = TPS7B6933QDBVRQ1: High Voltage Ultra Low Iq - Low Drop Out Regulator, DBV0005A (SOT-23-5); Manufacturer: Texas Instruments; SymbolCreator: Altium; SizeArea_mm2: 8.12; SizeAreaWB_mm2: 14.82; SizeX_mm: 2.8; SizeY_mm: 2.9; SizeZ_mm: 1.45; CompType: IC; U/M: EA
U4 U6 = CMP-0076106-1: Automotive Brushed DC Motor Gate Driver, RHB0032E (VQFN-32); Alternate PartNumber: DRV8702DQRHBTQ1; Alternate Manufacturer: Texas Instruments; SizeX_mm: 5.0; CompType: IC; SizeAreaWB_mm2: 49.0; SizeZ_mm: 1.0; U/M: EA; SizeArea_mm2: 25.0

## Sheet TIDA01530 Rear Wipers.SchDoc
size 431 x 279 mm; Date: Not shown in title block; ApprovedBy: Not shown in title block; CheckedBy: Not shown in title block; Author: Not shown in title block; CompanyName: Not shown in title block; Engineer: Not shown in title block; Organization: Not shown in title block; Address1: Not shown in title block; Address2: Not shown in title block; Address3: Not shown in title block; Address4: Not shown in title block; DocumentNumber: 1; Revision: Use project parameter SCH_Rev; SheetNumber: 3; SheetTotal: 4; PageSetup: Record=PageOptions¦CenterHorizontal=True¦CenterVertical=True¦PrintScale=1.00¦XCorrection=1.00¦YCorrection=1.00¦PrintKind=0¦BorderSize=5000000¦LeftOffset=0¦BottomOffset=0¦Orientation=2¦PaperLength=1000¦PaperWidth=1000¦Scale=100¦PaperSource=15¦PrintQuality=600¦MediaType=1¦DitherType=10¦PaperKind=Letter¦PrintScaleMode=1
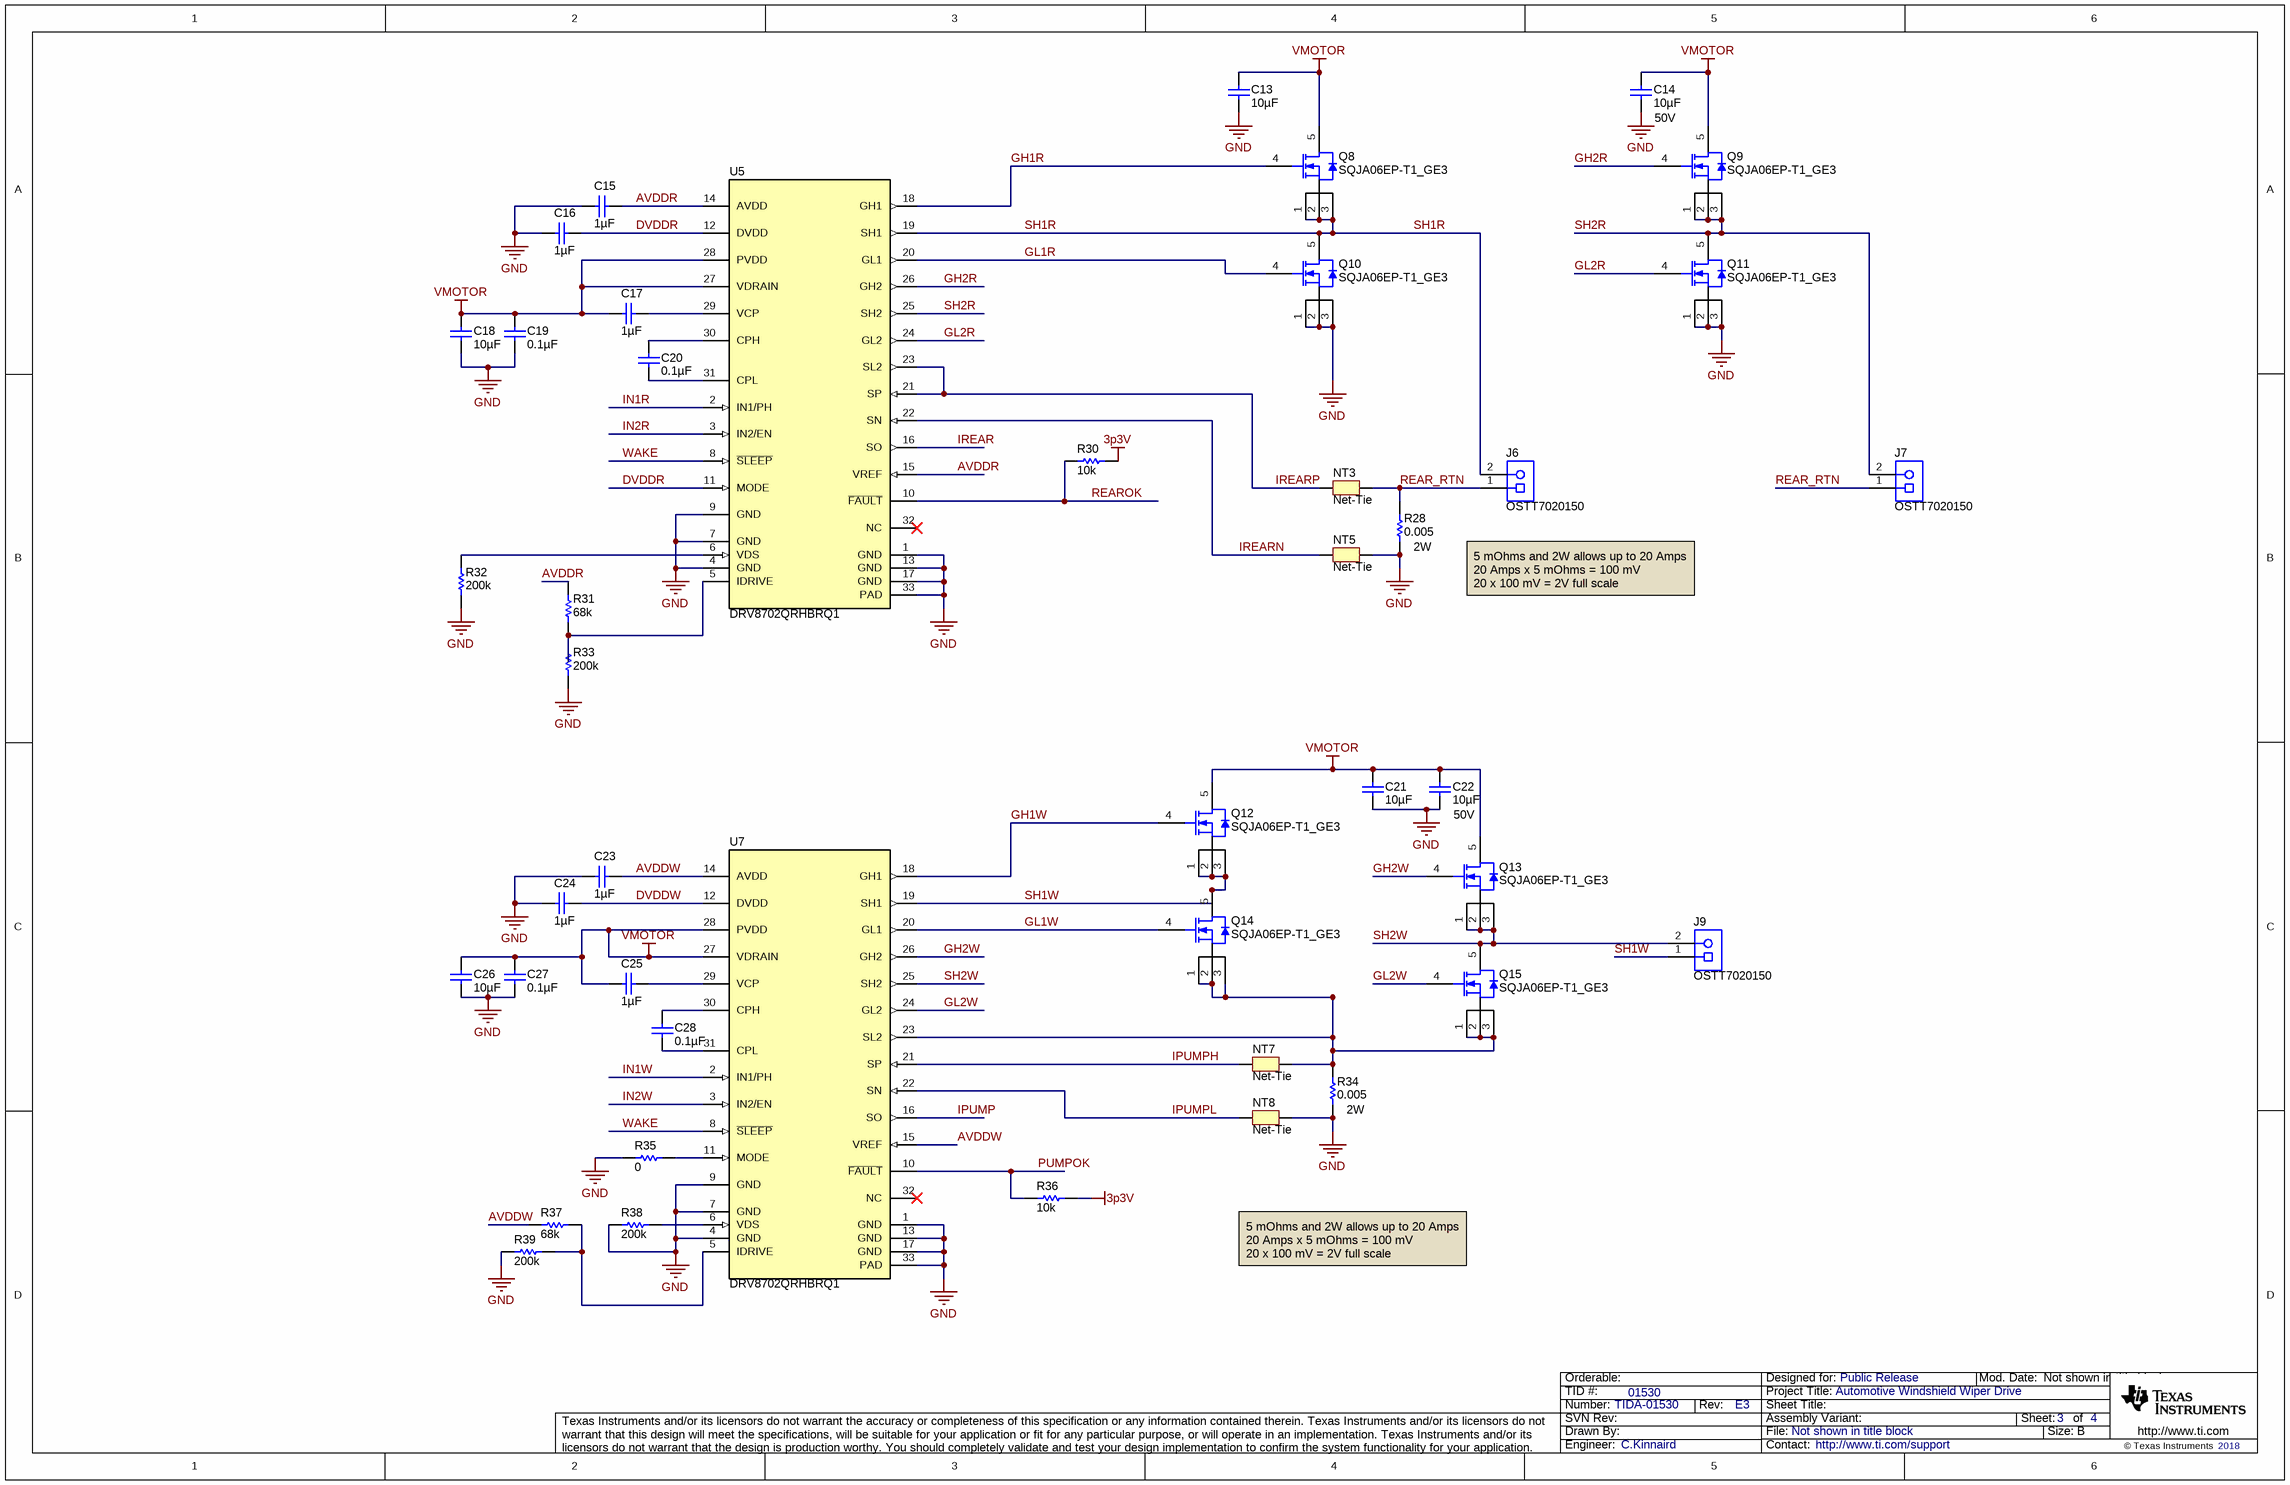
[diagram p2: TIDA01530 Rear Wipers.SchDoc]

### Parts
C13  ValueDisplayed: 10µF  [1206_180]  (hidden comment: CL31B106KBHNNNE)
C14  ValueDisplayed: 10µF  Value2: 50V  [1206_180]  (hidden comment: CL31B106KBHNNNE)
C15  ValueDisplayed: 1µF  [0603]  (hidden comment: GRM188R70J105KA01D)
C16  ValueDisplayed: 1µF  [0603]  (hidden comment: GRM188R70J105KA01D)
C17  ValueDisplayed: 1µF  [0603]  (hidden comment: C1608X7R1C105K080AC)
C18  ValueDisplayed: 10µF  [1210_280]  (hidden comment: C3225X7S1H106K250AB)
C19  ValueDisplayed: 0.1µF  [0603]  (hidden comment: C1608X7R1H104K080AA)
C20  ValueDisplayed: 0.1µF  [0603]  (hidden comment: C1608X7R1H104K080AA)
C21  ValueDisplayed: 10µF  [1206_180]  (hidden comment: CL31B106KBHNNNE)
C22  ValueDisplayed: 10µF  Value2: 50V  [1206_180]  (hidden comment: CL31B106KBHNNNE)
C23  ValueDisplayed: 1µF  [0603]  (hidden comment: GRM188R70J105KA01D)
C24  ValueDisplayed: 1µF  [0603]  (hidden comment: GRM188R70J105KA01D)
C25  ValueDisplayed: 1µF  [0603]  (hidden comment: C1608X7R1C105K080AC)
C26  ValueDisplayed: 10µF  [1210_280]  (hidden comment: C3225X7S1H106K250AB)
C27  ValueDisplayed: 0.1µF  [0603]  (hidden comment: C1608X7R1H104K080AA)
C28  ValueDisplayed: 0.1µF  [0603]  (hidden comment: C1608X7R1H104K080AA)
J6  OSTT7020150  [On-Shore_OSTT7020150]
J7  OSTT7020150  [On-Shore_OSTT7020150]
J9  OSTT7020150  [On-Shore_OSTT7020150]
NT3  Net-Tie  [Net-Tie_10mil]  (net tie, no BOM)
NT5  Net-Tie  [Net-Tie_10mil]  (net tie, no BOM)
NT7  Net-Tie  [Net-Tie_10mil]  (net tie, no BOM)
NT8  Net-Tie  [Net-Tie_10mil]  (net tie, no BOM)
Q8  SQJA06EP-T1_GE3  [PowerPAK_SO-8L]
Q9  SQJA06EP-T1_GE3  [PowerPAK_SO-8L]
Q10  SQJA06EP-T1_GE3  [PowerPAK_SO-8L]
Q11  SQJA06EP-T1_GE3  [PowerPAK_SO-8L]
Q12  SQJA06EP-T1_GE3  [PowerPAK_SO-8L]
Q13  SQJA06EP-T1_GE3  [PowerPAK_SO-8L]
Q14  SQJA06EP-T1_GE3  [PowerPAK_SO-8L]
Q15  SQJA06EP-T1_GE3  [PowerPAK_SO-8L]
R28  ValueDisplayed: 0.005  Value2: 2W  [2512]  (hidden comment: MCS3264R005FER)
R30  ValueDisplayed: 10k  [0402]  (hidden comment: CRCW040210K0JNED)
R31  ValueDisplayed: 68k  [0402]  (hidden comment: CRCW040268K0JNED)
R32  ValueDisplayed: 200k  [0402]  (hidden comment: CRCW0402200KJNED)
R33  ValueDisplayed: 200k  [0402]  (hidden comment: CRCW0402200KJNED)
R34  ValueDisplayed: 0.005  Value2: 2W  [2512]  (hidden comment: MCS3264R005FER)
R35  ValueDisplayed: 0  [0402]  (hidden comment: ERJ-2GE0R00X)
R36  ValueDisplayed: 10k  [0402]  (hidden comment: CRCW040210K0JNED)
R37  ValueDisplayed: 68k  [0402]  (hidden comment: CRCW040268K0JNED)
R38  ValueDisplayed: 200k  [0402]  (hidden comment: CRCW0402200KJNED)
R39  ValueDisplayed: 200k  [0402]  (hidden comment: CRCW0402200KJNED)
U5  DRV8702QRHBRQ1  [RHB0032E]
U7  DRV8702QRHBRQ1  [RHB0032E]

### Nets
3p3V: R30.1 R36.1
GND: C13.2 C14.2 C15.2 C16.2 C18.2 C19.2 C21.2 C22.2 C23.2 C24.2 C26.2 C27.2 NT5.2 NT8.2 Q10.1(S) Q10.2(S) Q10.3(S) Q11.1(S) Q11.2(S) Q11.3(S) R28.1 R32.2 R33.2 R34.1 R35.1 R38.2 R39.2 U5.1(GND) U5.4(GND) U5.7(GND) U5.9(GND) U5.13(GND) U5.17(GND) U5.33(PAD) U7.1(GND) U7.4(GND) U7.7(GND) U7.9(GND) U7.13(GND) U7.17(GND) U7.33(PAD)
VMOTOR: C13.1 C14.1 C17.1 C18.1 C19.1 C21.1 C22.1 C25.1 C26.1 C27.1 Q8.5(D) Q9.5(D) Q12.5(D) Q13.5(D) U5.27(VDRAIN) U5.28(PVDD) U7.27(VDRAIN) U7.28(PVDD)
AVDDR: C15.1 R31.1 U5.14(AVDD) U5.15(VREF)
AVDDW: C23.1 R37.2 U7.14(AVDD) U7.15(VREF)
DVDDR: C16.1 U5.11(MODE) U5.12(DVDD)
DVDDW: C24.1 U7.12(DVDD)
GH1R: Q8.4(G) U5.18(GH1)
GH1W: Q12.4(G) U7.18(GH1)
GH2R: Q9.4(G) U5.26(GH2)
GH2W: Q13.4(G) U7.26(GH2)
GL1R: Q10.4(G) U5.20(GL1)
GL1W: Q14.4(G) U7.20(GL1)
GL2R: Q11.4(G) U5.24(GL2)
GL2W: Q15.4(G) U7.24(GL2)
IN1R: U5.2(IN1/PH)
IN1W: U7.2(IN1/PH)
IN2R: U5.3(IN2/EN)
IN2W: U7.3(IN2/EN)
IPUMP: U7.16(SO)
IPUMPH: NT7.1 U7.21(SP)
IPUMPL: NT8.1 U7.22(SN)
IREAR: U5.16(SO)
IREARN: NT5.1 U5.22(SN)
IREARP: NT3.1 U5.21(SP) U5.23(SL2)
PUMPOK: R36.2 U7.10(~{FAULT})
REAR_RTN: J6.1 J7.1 NT3.2 R28.2
REAROK: R30.2 U5.10(~{FAULT})
SH1R: J6.2 Q8.1(S) Q8.2(S) Q8.3(S) Q10.5(D) U5.19(SH1)
SH1W: J9.1 Q12.1(S) Q12.2(S) Q12.3(S) Q14.5(D) U7.19(SH1)
SH2R: J7.2 Q9.1(S) Q9.2(S) Q9.3(S) Q11.5(D) U5.25(SH2)
SH2W: J9.2 Q13.1(S) Q13.2(S) Q13.3(S) Q15.5(D) U7.25(SH2)
WAKE: U5.8(~{SLEEP}) U7.8(~{SLEEP})
NetC17_2: C17.2 U5.29(VCP)
NetC20_1: C20.1 U5.30(CPH)
NetC20_2: C20.2 U5.31(CPL)
NetC25_2: C25.2 U7.29(VCP)
NetC28_1: C28.1 U7.30(CPH)
NetC28_2: C28.2 U7.31(CPL)
NetNT7_2: NT7.2 Q14.1(S) Q14.2(S) Q14.3(S) Q15.1(S) Q15.2(S) Q15.3(S) R34.2 U7.23(SL2)
NetR31_2: R31.2 R33.1 U5.5(IDRIVE)
NetR32_1: R32.1 U5.6(VDS)
NetR35_2: R35.2 U7.11(MODE)
NetR37_1: R37.1 R39.1 U7.5(IDRIVE)
NetR38_1: R38.1 U7.6(VDS)

Not connected (* = marked no-connect by the designer): U5 32(NC)*; U7 32(NC)*

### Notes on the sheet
- 5 mOhms and 2W allows up to 20 Amps
  20 Amps x 5 mOhms = 100 mV
  20 x 100 mV = 2V full scale

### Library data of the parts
C13 C21 = CL31B106KBHNNNE: as C5 on sheet TIDA01530 Front Wipers 2x 8702D v2
C14 C22 = CL31B106KBHNNNE: as C6 on sheet TIDA01530 Front Wipers 2x 8702D v2
C15 C16 C23 C24 = GRM188R70J105KA01D: CAP, CERM, 1 µF, 6.3 V,+/- 10%, X7R, 0603; Manufacturer: MuRata; Polarized: N; CompType: Capacitor; Value: 1uF; U/M: EA; Cap_F: 0.000001; Tolerance_%: 10; VDC_V: 6.3; Value2: 6.3V; TaMin_C: -55; TaMax_C: 125; SizeArea_mm2: 1.28; SizeAreaWB_mm2: 4.68; SizeX_mm: 1.6; SizeY_mm: 0.8; SizeZ_mm: 1; AEC Category: Q200; Green_Lifecycle: Active; Green_REACh: Passed
C17 C25 = C1608X7R1C105K080AC: CAP, CERM, 1 µF, 16 V,+/- 10%, X7R, 0603; Manufacturer: TDK; Polarized: N; CompType: Capacitor; Value: 1uF; U/M: EA; Cap_F: 0.000001; Tolerance_%: 10; ESR_ohm: 0.0057; Value1: 0.0057 ohm; VDC_V: 16; Value2: 16V; TaMin_C: -55; TaMax_C: 125; SizeArea_mm2: 1.28; SizeAreaWB_mm2: 4.68; SizeX_mm: 1.6; SizeY_mm: 0.8; SizeZ_mm: 1; AEC Category: Q200; Green_Lifecycle: Active; Green_REACh: Passed
C18 C26 = C3225X7S1H106K250AB: CAP, CERM, 10 µF, 50 V,+/- 10%, X7S, 1210; Manufacturer: TDK; Polarized: N; CompType: Capacitor; Value: 10uF; U/M: EA; Cap_F: 0.00001; Tolerance_%: 10; ESR_ohm: 0.002827; Value1: 0.002827 ohm; VDC_V: 50; Value2: 50V; IRMS_A: 4.37286; TaMin_C: -55; TaMax_C: 125; Cap_Case: 1210; SizeArea_mm2: 8; SizeAreaWB_mm2: 14.7; SizeX_mm: 3.2; SizeY_mm: 2.5; SizeZ_mm: 2.8; AEC Category: Q200; Green_Lifecycle: Active; Green_REACh: Passed
C19 C20 C27 C28 = C1608X7R1H104K080AA: CAP, CERM, 0.1 µF, 50 V,+/- 10%, X7R, 0603; Manufacturer: TDK; Polarized: N; CompType: Capacitor; Value: 0.1uF; U/M: EA; Cap_F: 0.0000001; Tolerance_%: 10; ESR_ohm: 0.0296; Value1: 0.0296 ohm; VDC_V: 50; Value2: 50V; IRMS_A: 0.97199; TaMin_C: -55; TaMax_C: 125; SizeArea_mm2: 1.28; SizeAreaWB_mm2: 4.68; SizeX_mm: 1.6; SizeY_mm: 0.8; SizeZ_mm: 1; AEC Category: Q200; Green_Lifecycle: NRND; Green_REACh: Passed
J6 J7 J9 = OSTT7020150: Terminal Block, 6.35mm, 2x1, TH; Manufacturer: On-Shore Technology; SymbolCreator: a0412235; Pitch_mm: 6.35; Gender: Female; Row_Count: 1; Current_A: 30; Voltage_V: 300; Cert_UL: Y
NT3 NT5 NT7 NT8 = Net-Tie: as NT1 on sheet TIDA01530 Front Wipers 2x 8702D v2
Q8-Q15 = CMP-0077287-1: as Q3 on sheet TIDA01530 Front Wipers 2x 8702D v2
R28 R34 = MCS3264R005FER: RES, 0.005, 1%, 2 W, 2512; Manufacturer: Ohmite; CompType: Resistor; Value: 0.005; Value_Code: 5L000; Tolerance_%: 1; Power_W: 2; TempCo: 50 ppm/C; SizeArea_mm2: 20.16; SizeX_mm: 6.3; SizeY_mm: 3.2; SizeZ_mm: 0.71; EIA_Code: E96; U/M: EA; AEC Category: Q200
R30 R36 = CRCW040210K0JNED: as R2 on sheet TIDA01530 Front Wipers 2x 8702D v2
R31 R37 = CRCW040268K0JNED: as R23 on sheet TIDA01530 Front Wipers 2x 8702D v2
R32 R33 R38 R39 = CRCW0402200KJNED: as R24 on sheet TIDA01530 Front Wipers 2x 8702D v2
R35 = ERJ-2GE0R00X: as R4 on sheet TIDA01530 Front Wipers 2x 8702D v2
U5 U7 = DRV8702QRHBRQ1: Automotive Brushed DC Motor Gate Driver, RHB0032E (VQFN-32); Alternate PartNumber: DRV8702QRHBTQ1; Manufacturer: Texas Instruments; SymbolCreator: Altium; SizeArea_mm2: 25; SizeAreaWB_mm2: 49; SizeX_mm: 5; SizeZ_mm: 1; CompType: IC; U/M: EA; Green_Lifecycle: Active; Green_REACh: Passed

## Sheet TIDA01530 Switches Connectors.SchDoc
size 431 x 279 mm; Date: Not shown in title block; ApprovedBy: Not shown in title block; CheckedBy: Not shown in title block; Author: Not shown in title block; CompanyName: Not shown in title block; Engineer: Not shown in title block; Organization: Not shown in title block; Address1: Not shown in title block; Address2: Not shown in title block; Address3: Not shown in title block; Address4: Not shown in title block; DocumentNumber: 1; Revision: Use project parameter SCH_Rev; SheetNumber: 4; SheetTotal: 4; PageSetup: Record=PageOptions¦CenterHorizontal=True¦CenterVertical=True¦PrintScale=1.00¦XCorrection=1.00¦YCorrection=1.00¦PrintKind=0¦BorderSize=5000000¦LeftOffset=0¦BottomOffset=0¦Orientation=2¦PaperLength=1000¦PaperWidth=1000¦Scale=100¦PaperSource=15¦PrintQuality=600¦MediaType=1¦DitherType=10¦PaperKind=Letter¦PrintScaleMode=1
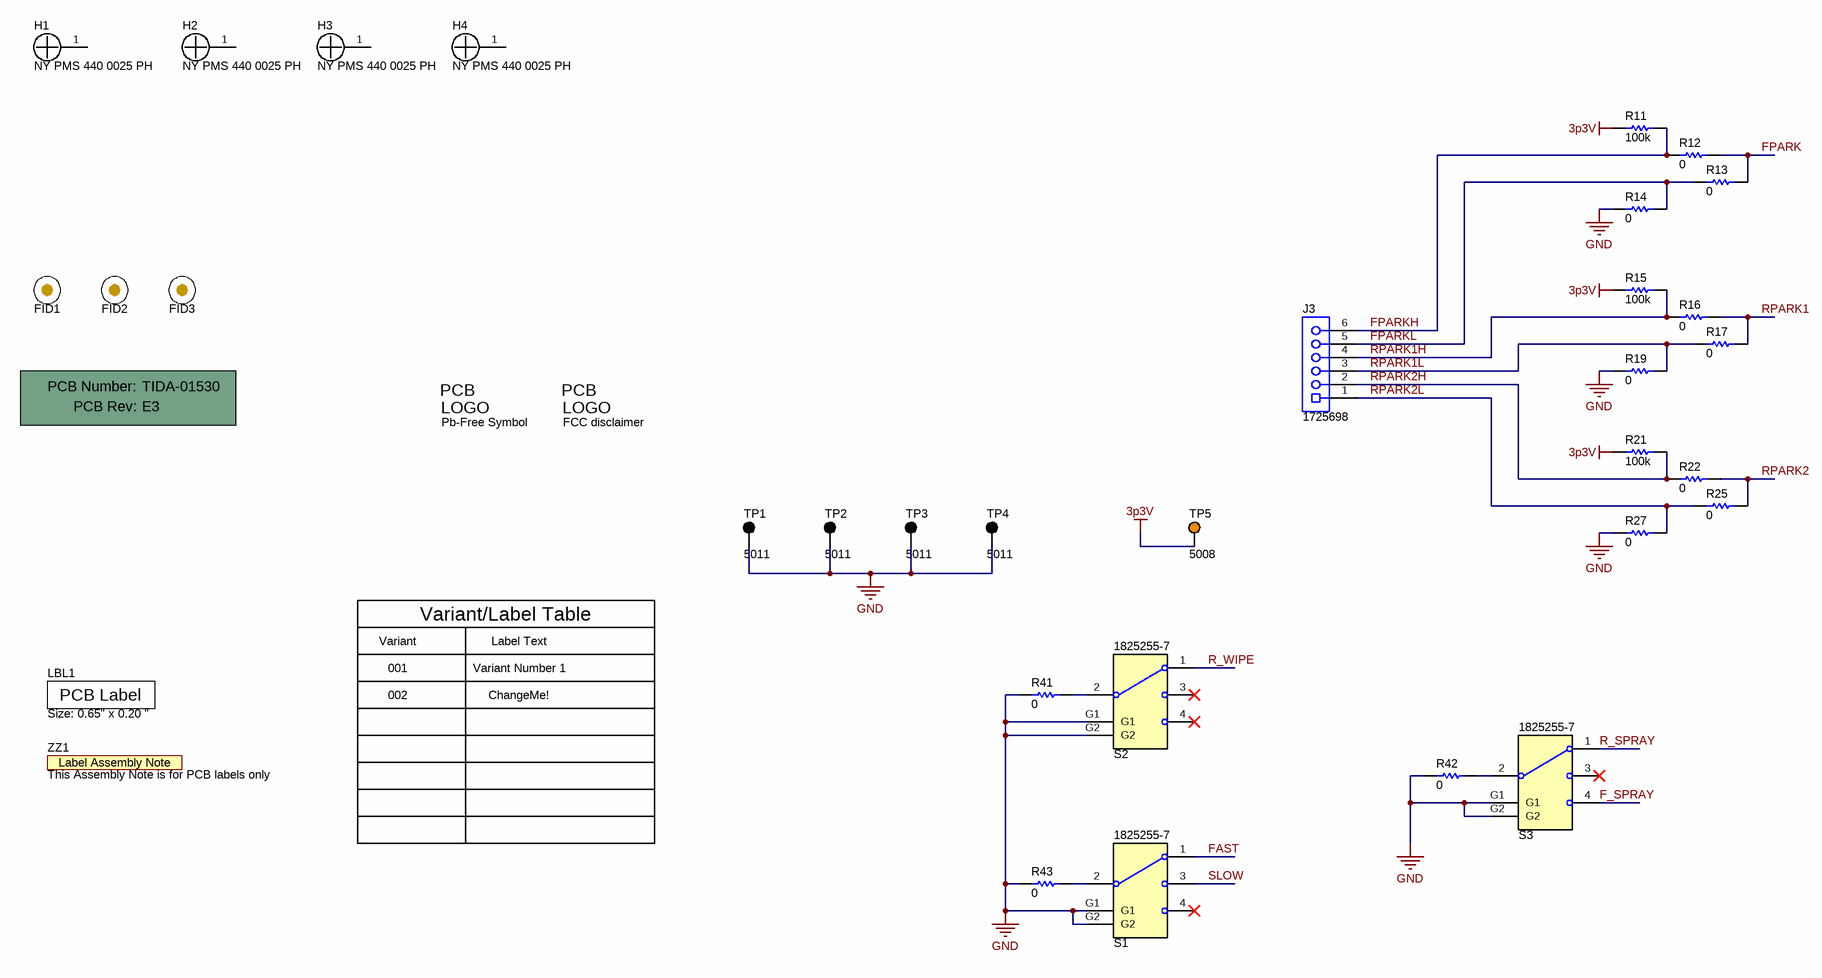
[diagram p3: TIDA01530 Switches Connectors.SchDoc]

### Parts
!PCB1  Printed Circuit Board  (value not drawn)  (mechanical)
FID1  Fiducial  [Fiducial10-20]  (value not drawn)
FID2  Fiducial  [Fiducial10-20]  (value not drawn)
FID3  Fiducial  [Fiducial10-20]  (value not drawn)
H1  NY PMS 440 0025 PH  [NY PMS 440 0025 PH]
H2  NY PMS 440 0025 PH  [NY PMS 440 0025 PH]
H3  NY PMS 440 0025 PH  [NY PMS 440 0025 PH]
H4  NY PMS 440 0025 PH  [NY PMS 440 0025 PH]
J3  1725698  [Phoenix_1725698]
LBL1  Size: 0.65" x 0.20 "  [Label_650x200]
Logo2  Pb-Free Symbol  [Pb-Free_Overlay_Small]  (no BOM)
Logo3  FCC disclaimer  [FCC_disclaimer]  (no BOM)
R11  ValueDisplayed: 100k  [0402]  (hidden comment: CRCW0402100KJNED)
R12  ValueDisplayed: 0  [0402]  (hidden comment: ERJ-2GE0R00X)
R13  ValueDisplayed: 0  [0402]  (hidden comment: ERJ-2GE0R00X)
R14  ValueDisplayed: 0  [0402]  (hidden comment: ERJ-2GE0R00X)
R15  ValueDisplayed: 100k  [0402]  (hidden comment: CRCW0402100KJNED)
R16  ValueDisplayed: 0  [0402]  (hidden comment: ERJ-2GE0R00X)
R17  ValueDisplayed: 0  [0402]  (hidden comment: ERJ-2GE0R00X)
R19  ValueDisplayed: 0  [0402]  (hidden comment: ERJ-2GE0R00X)
R21  ValueDisplayed: 100k  [0402]  (hidden comment: CRCW0402100KJNED)
R22  ValueDisplayed: 0  [0402]  (hidden comment: ERJ-2GE0R00X)
R25  ValueDisplayed: 0  [0402]  (hidden comment: ERJ-2GE0R00X)
R27  ValueDisplayed: 0  [0402]  (hidden comment: ERJ-2GE0R00X)
R41  ValueDisplayed: 0  [0402]  (hidden comment: ERJ-2GE0R00X)
R42  ValueDisplayed: 0  [0402]  (hidden comment: ERJ-2GE0R00X)
R43  ValueDisplayed: 0  [0402]  (hidden comment: ERJ-2GE0R00X)
S1  1825255-7  [SW_1825255-8]
S2  1825255-7  [SW_1825255-8]
S3  1825255-7  [SW_1825255-8]
TP1  5011  [Keystone5011]
TP2  5011  [Keystone5011]
TP3  5011  [Keystone5011]
TP4  5011  [Keystone5011]
TP5  5008  [Keystone5008]
ZZ1  This Assembly Note is for PCB labels only  [AssemblyNoteLabel]  (no BOM)

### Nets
3p3V: R11.1 R15.1 R21.1 TP5.1
GND: R14.1 R19.1 R27.1 R41.1 R42.1 R43.1 S1.G1 S1.G2 S2.G1 S2.G2 S3.G1 S3.G2 TP1.1 TP2.1 TP3.1 TP4.1
F_SPRAY: S3.4
FAST: S1.1
FPARK: R12.2 R13.2
FPARKH: J3.6 R11.2 R12.1
FPARKL: J3.5 R13.1 R14.2
R_SPRAY: S3.1
R_WIPE: S2.1
RPARK1: R16.2 R17.2
RPARK1H: J3.4 R15.2 R16.1
RPARK1L: J3.3 R17.1 R19.2
RPARK2: R22.2 R25.2
RPARK2H: J3.2 R21.2 R22.1
RPARK2L: J3.1 R25.1 R27.2
SLOW: S1.3
NetR41_2: R41.2 S2.2
NetR42_2: R42.2 S3.2
NetR43_2: R43.2 S1.2

Not connected (* = marked no-connect by the designer): H1 1; H2 1; H3 1; H4 1; S1 4*; S2 3* 4*; S3 3*

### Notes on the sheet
- Variant
- Variant/Label Table
- Label Text
- 001
- 002
- Variant Number 1
- ChangeMe!

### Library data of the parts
!PCB1 = PCB: Manufacturer: Any; PartNumber: TIDA-01530; SymbolCreator: a0412235
FID1-FID3 = Fiducial: Fiducial mark.  There is nothing to buy or mount.; SymbolCreator: codlsc
H1-H4 = NY PMS 440 0025 PH: Machine Screw, Round, #4-40 x 1/4, Nylon, Philips panhead; Manufacturer: B&F Fastener Supply; CompType: Hardware; SymbolCreator: codlsc; U/M: EA
J3 = CMP-0055512-1: Terminal Block, 6x1, 2.54mm, TH; Manufacturer: Phoenix Contact; CNHeader: FALSE; Current_A: 6A; Cert_CSA: Y; Voltage_V: 160V; Row_Count: 1; Pitch_mm: 2.54; CT: TRUE
LBL1 = THT-14-423-10: Thermal Transfer Printable Labels, 0.650" W x 0.200" H - 10,000 per roll; Manufacturer: Brady; SymbolCreator: a0412235; CompType: Label
Logo2 = Pb-Free: SymbolCreator: a0412235
Logo3 = FCC_disclaimer: SymbolCreator: codlsc
R11 R15 R21 = CRCW0402100KJNED: RES, 100 k, 5%, 0.063 W, 0402; Manufacturer: Vishay-Dale; CompType: Resistor; Value: 100k; Res_ohm: 100000; Tolerance_%: 5; Power_W: 0.063; Value2: 0.063W; VDC_V: 50; TempCo: 200 ppm/C; SizeArea_mm2: 0.5; SizeX_mm: 1; SizeZ_mm: 0.6; EIA_Code: E24; U/M: EA; AEC Category: Q200; Green_Lifecycle: Active; Green_REACh: Passed
R12-R14 R16 R17 R19 R22 R25 R27 R41-R43 = ERJ-2GE0R00X: as R4 on sheet TIDA01530 Front Wipers 2x 8702D v2
S1-S3 = 1825255-7: Switch, Slide, SP3T, 3 Pos, 0.3 A, 125 VAC, TH; Manufacturer: TE Connectivity; SymbolCreator: Altium; SwitchFunction: On-On-On; PositionCount: 3; CurrentRating_mA: 300
TP1-TP4 = CMP-0055148-1: Test Point, Multipurpose, Black, TH; Manufacturer: Keystone; CNHeader: FALSE; Green_Lifecycle: Active; Green_REACh: Passed; ContactFinish: Silver; CT: TRUE
TP5 = CMP-0055145-1: Test Point, Compact, Orange, TH; Manufacturer: Keystone; CNHeader: FALSE; Green_Lifecycle: Active; Green_REACh: Passed; ContactFinish: Silver; CT: TRUE
ZZ1 = AssemblyNoteLabel: SymbolCreator: a0412235

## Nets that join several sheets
3p3V: TIDA01530 Front Wipers 2x 8702D v2 (14 pins), TIDA01530 Rear Wipers (R30.1 R36.1), TIDA01530 Switches Connectors (R11.1 R15.1 R21.1 TP5.1)
GND: TIDA01530 Front Wipers 2x 8702D v2 (59 pins), TIDA01530 Rear Wipers (41 pins), TIDA01530 Switches Connectors (16 pins)
VMOTOR: TIDA01530 Front Wipers 2x 8702D v2 (16 pins), TIDA01530 Rear Wipers (18 pins)
F_SPRAY: TIDA01530 Front Wipers 2x 8702D v2 (J4.6), TIDA01530 Switches Connectors (S3.4)
FAST: TIDA01530 Front Wipers 2x 8702D v2 (J5.4), TIDA01530 Switches Connectors (S1.1)
FPARK: TIDA01530 Front Wipers 2x 8702D v2 (J4.14), TIDA01530 Switches Connectors (R12.2 R13.2)
IN1R: TIDA01530 Front Wipers 2x 8702D v2 (J5.18), TIDA01530 Rear Wipers (U5.2)
IN1W: TIDA01530 Front Wipers 2x 8702D v2 (J4.17), TIDA01530 Rear Wipers (U7.2)
IN2R: TIDA01530 Front Wipers 2x 8702D v2 (J5.16), TIDA01530 Rear Wipers (U5.3)
IN2W: TIDA01530 Front Wipers 2x 8702D v2 (J4.19), TIDA01530 Rear Wipers (U7.3)
IPUMP: TIDA01530 Front Wipers 2x 8702D v2 (J4.15), TIDA01530 Rear Wipers (U7.16)
IREAR: TIDA01530 Front Wipers 2x 8702D v2 (J4.13), TIDA01530 Rear Wipers (U5.16)
PUMPOK: TIDA01530 Front Wipers 2x 8702D v2 (J4.9), TIDA01530 Rear Wipers (R36.2 U7.10)
R_SPRAY: TIDA01530 Front Wipers 2x 8702D v2 (J4.8), TIDA01530 Switches Connectors (S3.1)
R_WIPE: TIDA01530 Front Wipers 2x 8702D v2 (J4.7), TIDA01530 Switches Connectors (S2.1)
REAROK: TIDA01530 Front Wipers 2x 8702D v2 (J5.14), TIDA01530 Rear Wipers (R30.2 U5.10)
RPARK1: TIDA01530 Front Wipers 2x 8702D v2 (J4.18), TIDA01530 Switches Connectors (R16.2 R17.2)
RPARK2: TIDA01530 Front Wipers 2x 8702D v2 (J4.20), TIDA01530 Switches Connectors (R22.2 R25.2)
SLOW: TIDA01530 Front Wipers 2x 8702D v2 (J5.6), TIDA01530 Switches Connectors (S1.3)
WAKE: TIDA01530 Front Wipers 2x 8702D v2 (J5.2 U1.4 U6.8), TIDA01530 Rear Wipers (U5.8 U7.8)

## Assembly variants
001: not fitted FID1 FID2 FID3 R13 R14 R17 R23 R24 R25 R31 R37 R45 R47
